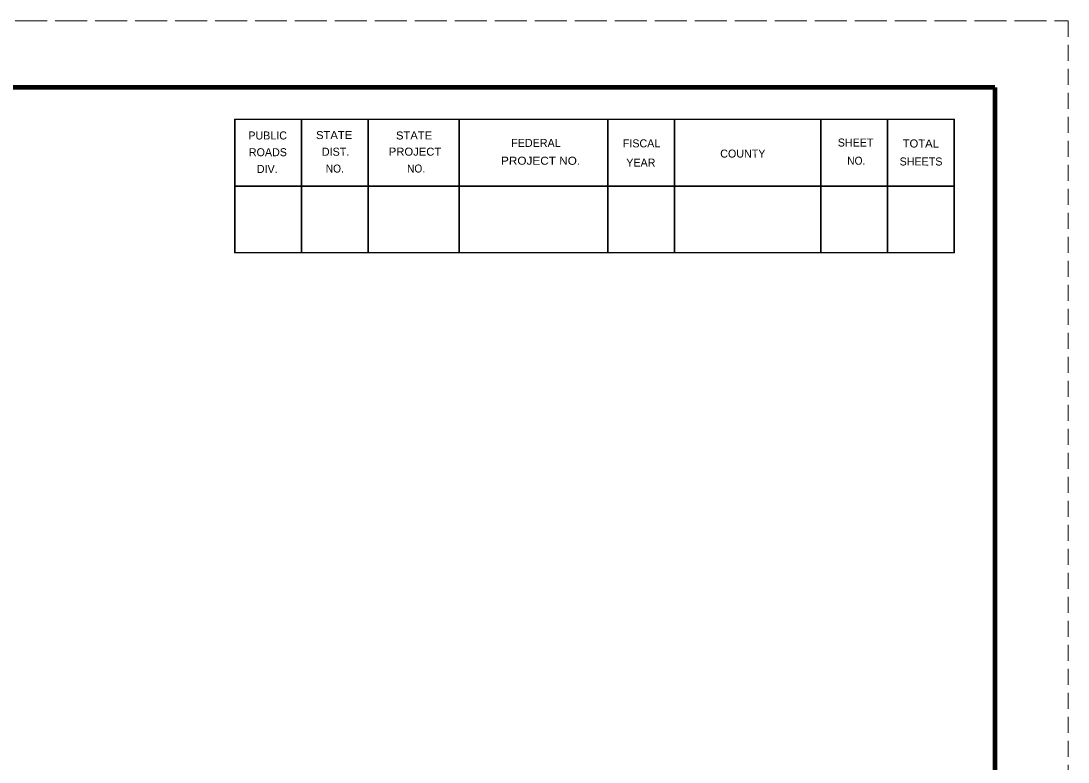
# Model space of a CAD drawing. Extents: x -280 to 400, y 15 to 456.
# Drawn here: x 243 to 400.2, y 344.4 to 455.5 of the extents above; entities that cross this region are included whole.
import ezdxf

# ---------------------------------------------------------------- set-up
doc = ezdxf.new("R2010")
doc.units = 0
doc.header["$LTSCALE"] = 0.8
doc.linetypes.add('LONG_DASHED', pattern=[7.5, 6, -1.5])
doc.linetypes.add('MEDIUM_DASHED', pattern=[4.5, 3, -1.5])
doc.layers.add('1', color=7, linetype='Continuous', lineweight=53)
doc.layers.add('61', color=7, linetype='Continuous', lineweight=35)

msp = doc.modelspace()

# ---------------------------------------------------------------- linework, layer by layer
at = {"layer": '1', "linetype": 'MEDIUM_DASHED', "lineweight": 13}
msp.add_line((400.1618, 455.5237), (400.1418, 15.5037), dxfattribs=at)
at = {"layer": '61', "linetype": 'LONG_DASHED', "lineweight": 13}
msp.add_line((-279.8582, 455.5237), (400.1618, 455.5237), dxfattribs=at)
at = {"layer": '61', "lineweight": 158}
msp.add_line((389.1818, 445.5237), (389.2018, 25.4837), dxfattribs=at)
at = {"layer": '61'}
for p, q in [((285.1018, 440.7637), (285.1018, 420.7637)), ((295.1018, 440.7637), (295.1018, 420.7637)), ((308.7818, 440.7637), (308.7818, 420.7637)), ((331.1018, 440.7637), (331.1018, 420.7637)), ((341.1018, 440.7637), (341.1018, 420.7637)), ((363.0818, 440.7837), (363.0818, 420.7837)), ((373.0818, 440.7837), (373.0818, 420.7837)), ((383.1018, 430.7437), (275.0818, 430.7637))]:
    msp.add_line(p, q, dxfattribs=at)
at = {"layer": '61', "lineweight": 158}
msp.add_lwpolyline([(389.1818, 445.5237), (-249.8582, 445.5237), (-249.8582, 25.5037)], dxfattribs=at)
at = {"layer": '61'}
for points in [[(383.0818, 440.7837), (275.1018, 440.7637), (275.1018, 420.7637)], [(383.0818, 440.7837), (383.0818, 420.7837), (275.1018, 420.7637)]]:
    msp.add_lwpolyline(points, dxfattribs=at)

# ---------------------------------------------------------------- texts
for s, rotation, p in [('PUBLIC', 0.033, (277.1418, 437.7437)), ('FEDERAL', 0.007, (316.6018, 436.6237)), ('FISCAL', 359.942, (333.3418, 436.5637)), ('SHEET', 0.059, (365.6018, 436.6837)), ('ROADS', 0.124, (277.2218, 435.2237)), ('DIST.', 0.056, (288.1818, 435.3037)), ('COUNTY', 0.069, (347.9618, 435.0237)), ('DIV.', 359.932, (278.4218, 432.7237)), ('YEAR', 0.105, (333.8618, 433.6637)), ('SHEETS', 359.959, (374.8818, 433.8437))]:
    msp.add_text(s, height=1.201, rotation=rotation, dxfattribs=at).set_placement(p)
for s, rotation, width, p in [('STATE', 0.059, 1.05, (287.3018, 437.8037)), ('STATE', 0.059, 1.05, (299.3018, 437.7437)), ('TOTAL', 359.926, 1.05, (375.3418, 436.5437)), ('PROJECT', 359.908, 1.05, (298.2218, 435.3237)), ('NO.', 359.852, 0.95, (288.7618, 432.7837)), ('NO.', 0.225, 0.95, (300.9618, 432.7837)), ('PROJECT NO.', 359.922, 1.1, (315.0618, 433.9637)), ('NO.', 359.852, 0.95, (367.0218, 433.9637))]:
    msp.add_text(s, height=1.201, rotation=rotation, dxfattribs=dict(at, width=width)).set_placement(p)

doc.saveas('drawing.dxf')
